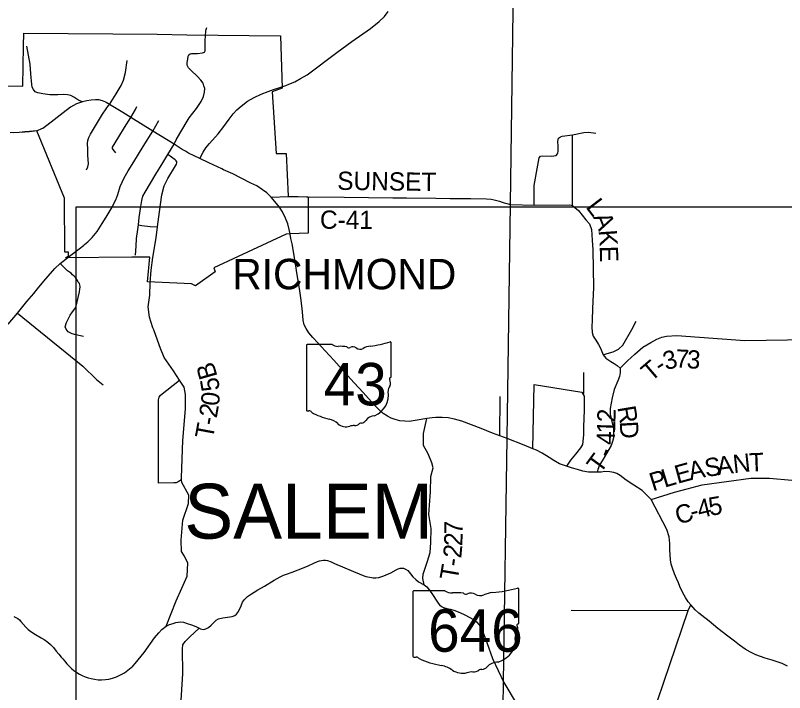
# Model space of a CAD drawing. Extents: x 2402298 to 2498138, y 789485 to 950881.
# Drawn here: x 2447192 to 2459820, y 881754 to 892870 of the extents above; entities that cross this region are included whole.
import ezdxf

# ---------------------------------------------------------------- set-up
doc = ezdxf.new("R2010")
doc.units = 0
for name, color, linetype in [('GM_X_City_Street', 7, 'Continuous'), ('GM_X_Corporation', 7, 'Continuous'), ('GM_X_Corporation_Text', 7, 'Continuous'), ('GM_X_County_Road', 7, 'Continuous'), ('GM_X_County_Road_Text', 7, 'Continuous'), ('GM_X_State_Route', 7, 'Continuous'), ('GM_X_State_Shield', 7, 'Continuous'), ('GM_X_Township', 7, 'Continuous'), ('GM_X_Township_Road', 7, 'Continuous'), ('GM_X_Township_Road_Text', 7, 'Continuous'), ('GM_X_Township_Text', 7, 'Continuous'), ('SH_Text', 7, 'Continuous')]:
    doc.layers.add(name, color=color, linetype=linetype)

msp = doc.modelspace()

# ---------------------------------------------------------------- linework, layer by layer
at = {"layer": 'GM_X_City_Street'}
msp.add_line((2449446, 890972), (2449548, 891146), dxfattribs=at)
for points in [[(2449164, 888933), (2449172, 889080), (2449179, 889207), (2449202, 889358), (2449215, 889434), (2449225, 889554), (2449249, 889734), (2449266, 889832), (2449286, 889901), (2449322, 889971), (2449499, 890265), (2449615, 890451), (2449697, 890586), (2449798, 890754), (2449834, 890825), (2449894, 890932), (2450047, 891186), (2450164, 891344), (2450240, 891455), (2450281, 891536), (2450299, 891607), (2450301, 891670), (2450287, 891712), (2450273, 891759), (2450235, 891808), (2450183, 891869), (2450073, 891972), (2450032, 892011), (2450014, 892053), (2450014, 892099), (2450022, 892151), (2450028, 892200), (2450040, 892225), (2450061, 892240), (2450082, 892247), (2450184, 892246), (2450263, 892253), (2450295, 892265), (2450309, 892290), (2450310, 892319), (2450310, 892434), (2450314, 892557), (2450317, 892591), (2450320, 892613), (2450326, 892637), (2450336, 892670)], [(2448292, 891452), (2448248, 891470), (2448200, 891497), (2448150, 891529), (2448101, 891553), (2448046, 891565), (2447987, 891569), (2447891, 891565), (2447760, 891564), (2447645, 891582), (2447561, 891598), (2447515, 891615), (2447487, 891652), (2447467, 891692), (2447462, 891737), (2447444, 891908), (2447436, 892069), (2447381, 892365)], [(2448357, 890333), (2448382, 890382), (2448391, 890434), (2448382, 890573), (2448380, 890674), (2448375, 890765), (2448381, 890815), (2448396, 890867), (2448423, 890919), (2448624, 891247), (2448681, 891338), (2448722, 891391), (2448738, 891407), (2448848, 891580), (2448927, 891718), (2448964, 891807), (2448998, 891931), (2449025, 892129)], [(2448841, 890613), (2448799, 890666), (2448786, 890687), (2448784, 890707), (2448889, 890876), (2448985, 891028), (2449088, 891192), (2449165, 891323), (2449186, 891375)], [(2449447, 888897), (2449504, 889218), (2449524, 889402), (2449560, 889643), (2449598, 889922), (2449637, 890072), (2449693, 890195), (2449820, 890398), (2449835, 890428), (2449842, 890448), (2449844, 890468), (2449834, 890485), (2449815, 890501), (2449697, 890586)], [(2449215, 889434), (2449268, 889419), (2449402, 889405), (2449524, 889402)]]:
    msp.add_lwpolyline(points, dxfattribs=at)
at = {"layer": 'GM_X_Corporation'}
msp.add_lwpolyline([(2446670, 891711), (2447313, 891708), (2447327, 892367), (2447333, 892576), (2449518, 892560), (2450009, 892551), (2451543, 892537), (2451569, 891675), (2451408, 891616), (2451471, 890604), (2451637, 890603), (2451669, 889901), (2451998, 889892), (2451998, 889298), (2451701, 889283), (2451638, 889279), (2450447, 888724), (2450472, 888663), (2450148, 888432), (2450083, 888465), (2449361, 888496), (2449397, 888901), (2449106, 888904), (2448017, 888889), (2448066, 888926), (2448066, 888981), (2448002, 888981), (2447996, 889869), (2447546, 890977), (2447425, 890963), (2447347, 890958), (2447252, 890950), (2447105, 890942)], dxfattribs=at)
at = {"layer": 'GM_X_County_Road'}
msp.add_line((2451708, 889897), (2451973, 889889), dxfattribs=at)
for points in [[(2451393, 889888), (2451670, 889898), (2451708, 889897)], [(2451973, 889889), (2451999, 889889), (2452588, 889887), (2453386, 889876), (2453612, 889875), (2454094, 889868), (2454332, 889862), (2454669, 889863), (2454928, 889860), (2455003, 889855), (2455051, 889845), (2455138, 889818), (2455181, 889805), (2455218, 889793), (2455237, 889788)], [(2455237, 889788), (2455262, 889781), (2455319, 889767), (2455709, 889755), (2456296, 889758), (2456337, 889748), (2456378, 889719), (2456434, 889669), (2456559, 889515), (2456614, 889446), (2456648, 889354), (2456658, 889178), (2456670, 889024), (2456680, 888403), (2456668, 888061), (2456659, 887869), (2456655, 887760), (2456659, 887665), (2456676, 887606), (2456718, 887538), (2456764, 887469), (2456800, 887407), (2456820, 887355), (2456841, 887297), (2456884, 887242), (2456966, 887188), (2457019, 887157), (2457069, 887125), (2457120, 887078), (2457120, 887006), (2457107, 886940), (2457080, 886873), (2457024, 886729), (2456989, 886594), (2456957, 886416), (2456955, 886323), (2456986, 886203), (2457013, 886082), (2457008, 885938), (2456996, 885876), (2456972, 885809), (2456855, 885615), (2456781, 885485), (2456752, 885415), (2456741, 885370)], [(2457627, 884923), (2458014, 885046), (2458222, 885097), (2458464, 885167), (2459267, 885275), (2459570, 885275), (2459938, 885242), (2460250, 885215), (2460668, 885203), (2461287, 885172), (2462299, 885114), (2462503, 885097), (2462703, 885107), (2463453, 885436), (2463907, 885464)]]:
    msp.add_lwpolyline(points, dxfattribs=at)
at = {"layer": 'GM_X_State_Route'}
for points in [[(2451680, 891739), (2451781, 891778), (2451873, 891836), (2451981, 891896), (2452470, 892261), (2452717, 892444), (2453024, 892656), (2453165, 892770), (2453250, 892849), (2453313, 892935)], [(2451430, 891651), (2451514, 891680), (2451634, 891721), (2451680, 891739)], [(2450221, 890521), (2450273, 890627), (2450317, 890696), (2450379, 890768), (2450521, 890927), (2450612, 891044), (2450700, 891167), (2450766, 891253), (2450827, 891319), (2450897, 891381), (2451005, 891460), (2451114, 891523), (2451224, 891577), (2451341, 891619), (2451430, 891651)], [(2448683, 891441), (2448678, 891444), (2448621, 891470), (2448561, 891484), (2448509, 891484), (2448438, 891476), (2448367, 891466), (2448292, 891452), (2448197, 891420), (2448098, 891364), (2447975, 891270), (2447830, 891154), (2447710, 891065), (2447641, 891016), (2447622, 891008)], [(2448953, 891275), (2448738, 891407), (2448683, 891441)], [(2449446, 890972), (2449088, 891192), (2448953, 891275)], [(2447622, 891008), (2447547, 890974), (2447426, 890960), (2447348, 890955), (2447253, 890947), (2447158, 890942)], [(2448329, 889107), (2448383, 889154), (2448455, 889224), (2448533, 889324), (2448615, 889455), (2448680, 889556), (2448766, 889696), (2448840, 889841), (2448871, 889932), (2448913, 890059), (2448976, 890205), (2449044, 890320), (2449137, 890467), (2449288, 890718), (2449446, 890972)], [(2449983, 890639), (2449929, 890670), (2449798, 890754), (2449446, 890972)], [(2450221, 890521), (2450033, 890611), (2449983, 890639)], [(2450609, 890336), (2450580, 890349), (2450367, 890449), (2450221, 890521)], [(2451701, 889285), (2451689, 889354), (2451664, 889449), (2451625, 889543), (2451575, 889646), (2451527, 889724), (2451451, 889816), (2451393, 889888), (2451318, 889958), (2451248, 890009), (2451154, 890073), (2451057, 890117), (2450900, 890200), (2450763, 890268), (2450609, 890336)], [(2457624, 884927), (2457544, 885014), (2457479, 885071), (2457344, 885158), (2457221, 885241), (2457122, 885315), (2457063, 885349), (2457017, 885368), (2456953, 885379), (2456866, 885381), (2456810, 885375), (2456741, 885370), (2456602, 885371), (2456505, 885390), (2456419, 885416), (2456338, 885439), (2456239, 885469), (2456126, 885510), (2456029, 885566), (2455953, 885615), (2455841, 885683), (2455748, 885735), (2455684, 885756), (2455546, 885813), (2455265, 885927), (2455143, 885969), (2455025, 886012), (2454840, 886087), (2454680, 886148), (2454523, 886210), (2454400, 886244), (2454295, 886263), (2454200, 886269), (2454096, 886270), (2454034, 886265), (2453948, 886255), (2453790, 886228), (2453656, 886206), (2453586, 886207), (2453503, 886217), (2453428, 886237), (2453360, 886260), (2453299, 886290), (2453230, 886336), (2453173, 886386), (2453101, 886458), (2452988, 886581), (2452899, 886681), (2452755, 886841), (2452588, 887022), (2452421, 887209), (2452279, 887362), (2452157, 887497), (2452077, 887582), (2452008, 887661), (2451963, 887732), (2451935, 887789), (2451915, 887866), (2451903, 888002), (2451885, 888195), (2451857, 888389), (2451818, 888612), (2451788, 888790), (2451755, 888992), (2451737, 889118), (2451715, 889208), (2451702, 889280), (2451701, 889285)], [(2448167, 888984), (2448309, 889091), (2448329, 889107)], [(2447074, 887802), (2447225, 887981), (2447382, 888172), (2447494, 888306), (2447557, 888380), (2447660, 888510), (2447729, 888592), (2447841, 888713), (2447927, 888796), (2448102, 888936), (2448167, 888984)], [(2459867, 882190), (2459777, 882234), (2459618, 882286), (2459503, 882319), (2459345, 882375), (2459258, 882418), (2459173, 882469), (2459080, 882534), (2458996, 882598), (2458890, 882680), (2458725, 882808), (2458583, 882925), (2458460, 883021), (2458411, 883058), (2458354, 883111), (2458282, 883194), (2458239, 883243), (2458194, 883314), (2458147, 883392), (2458099, 883498), (2458076, 883555), (2458046, 883627), (2458014, 883703), (2457979, 883797), (2457960, 883863), (2457944, 883932), (2457936, 884099), (2457933, 884204), (2457922, 884313), (2457888, 884433), (2457627, 884923), (2457624, 884927)], [(2449157, 882234), (2449308, 882411), (2449477, 882653), (2449546, 882733), (2449598, 882790), (2449666, 882844), (2449724, 882870), (2449780, 882889), (2449826, 882903), (2449864, 882912), (2449909, 882916), (2449952, 882912), (2450011, 882891), (2450084, 882865), (2450155, 882840), (2450207, 882812), (2450230, 882801), (2450253, 882795), (2450283, 882792), (2450319, 882801), (2450361, 882821), (2450404, 882862), (2450448, 882906), (2450488, 882942), (2450528, 882963), (2450599, 882982), (2450753, 883004), (2450796, 883020), (2450824, 883043), (2450854, 883085), (2450896, 883180), (2450922, 883236), (2450952, 883282), (2451001, 883330), (2451068, 883378), (2451114, 883405), (2451172, 883439), (2451280, 883501), (2451440, 883597), (2451539, 883654), (2451596, 883681), (2451644, 883700), (2451733, 883732), (2451907, 883795), (2452000, 883834), (2452093, 883879), (2452149, 883904), (2452185, 883916), (2452216, 883924), (2452251, 883929), (2452284, 883926), (2452318, 883920), (2452374, 883900), (2452432, 883875), (2452471, 883858), (2452564, 883818), (2452740, 883741), (2452835, 883702), (2452902, 883677), (2452945, 883662), (2453009, 883647), (2453063, 883638), (2453108, 883637), (2453157, 883646), (2453238, 883673), (2453357, 883721), (2453445, 883770), (2453476, 883787), (2453510, 883795), (2453538, 883798), (2453562, 883794), (2453597, 883782), (2453635, 883759), (2453678, 883701), (2453717, 883657), (2453764, 883611), (2453811, 883570), (2453902, 883522)], [(2453902, 883522), (2453948, 883489), (2454015, 883396), (2454061, 883329), (2454102, 883270), (2454133, 883222), (2454155, 883197), (2454188, 883169), (2454222, 883150), (2454273, 883136), (2454330, 883125), (2454391, 883108), (2454488, 883071), (2454569, 883032), (2454643, 882995), (2454711, 882955), (2454759, 882914), (2454802, 882872), (2454833, 882826), (2454849, 882789), (2454870, 882735), (2454932, 882575), (2455027, 882314), (2455208, 881922), (2455429, 881553)], [(2447164, 883002), (2447200, 882989), (2447233, 882971), (2447259, 882948), (2447283, 882921), (2447365, 882827), (2447403, 882790), (2447447, 882756), (2447523, 882709), (2447614, 882655), (2447665, 882625), (2447724, 882584), (2447770, 882542), (2447817, 882496), (2447862, 882436), (2447905, 882384), (2447945, 882337), (2447970, 882309)], [(2447970, 882309), (2447997, 882278), (2448037, 882227), (2448071, 882191), (2448112, 882152), (2448152, 882119), (2448203, 882082), (2448246, 882055), (2448287, 882035), (2448335, 882014), (2448384, 881997), (2448435, 881983), (2448492, 881973), (2448552, 881965), (2448607, 881964), (2448672, 881968), (2448728, 881976), (2448786, 881990), (2448850, 882013), (2448907, 882040), (2448982, 882079), (2449119, 882189), (2449157, 882234)]]:
    msp.add_lwpolyline(points, dxfattribs=at)
at = {"layer": 'GM_X_State_Shield'}
for p, q in [((2451970, 887451), (2451970, 886395)), ((2452391, 887470), (2451984, 887470)), ((2453362, 886943), (2453362, 887496)), ((2453362, 886943), (2453362, 886943)), ((2453718, 883408), (2453718, 882351)), ((2454244, 883426), (2453735, 883426)), ((2455458, 882899), (2455458, 883452)), ((2455458, 882899), (2455458, 882899))]:
    msp.add_line(p, q, dxfattribs=at)
for centre, radius, start, end in [((2452866, 888910), 1476, 275.8445, 288.9065), ((2453347, 887498), 15.5, 351.8621, 97.738), ((2451986, 887454), 16.1, 98.1301, 188.1301), ((2452488, 887592), 156, 231.6195, 271.1119), ((2452540, 886876), 562, 80.4867, 94.9883), ((2452668, 887459), 45.1, 219.7921, 297.1024), ((2452734, 887337), 93.8, 54.4667, 119.1411), ((2452855, 887505), 113, 233.8562, 294.8282), ((2453054, 887147), 297, 97.3462, 120.7689), ((2453358, 886902), 24, 107.944, 210.337), ((2453206, 886833), 144, 340.033, 23.6496), ((2453345, 886941), 16.6, 289.6038, 7.7341), ((2453417, 886712), 105, 136.8065, 186.9296), ((2452949, 886641), 369, 292.3089, 8.9858), ((2451986, 886392), 16.3, 171.9584, 258.3066), ((2451988, 886501), 124, 267.339, 280.6039), ((2452014, 886334), 44.8, 29.7484, 93.2717), ((2452579, 887283), 1066, 240.4129, 257.1985), ((2452261, 885920), 334, 47.1842, 75.836), ((2453104, 886098), 202, 94.4031, 142.5768), ((2452622, 886329), 212, 230.7004, 286.2918), ((2452744, 885963), 174, 85.6951, 111.2099), ((2452760, 886249), 113, 268.777, 315.5493), ((2452862, 886147), 31.8, 65.7517, 132.6484), ((2452848, 886292), 119, 282.8732, 323.2771)]:
    msp.add_arc(centre, radius, start, end, dxfattribs=at)
for centre, major_axis, start_param, end_param in [((2454838, 884866), (1845, 0), 4.814394, 5.042369), ((2455438, 883454), (19.4, 0), 6.141152, 7.989035), ((2453737, 883410), (20.2, 0), 1.712693, 3.28349), ((2454366, 883548), (196, 0), 4.042523, 4.731795), ((2454431, 882833), (702, 0), 1.404758, 1.657858), ((2454590, 883415), (56.4, 0), 3.836095, 5.185415), ((2454673, 883293), (117, 0), 0.950623, 2.079405), ((2454824, 883461), (141, 0), 4.081561, 5.145723), ((2455073, 883103), (371, 0), 1.699011, 2.107814), ((2455453, 882859), (30, 0), 1.883978, 3.671073), ((2455263, 882789), (180, 0), 5.934695, 6.695948), ((2455437, 882897), (20.7, 0), 5.05454, 6.418171), ((2455527, 882668), (131, 0), 2.387724, 3.262537), ((2454941, 882598), (462, 0), 5.101752, 6.440018), ((2453738, 882349), (20.3, 0), 3.00124, 4.508301), ((2453741, 882457), (155, 0), 4.665946, 4.897461), ((2453773, 882290), (56, 0), 0.519207, 1.627899), ((2454479, 883239), (1333, 0), 4.195997, 4.488961), ((2454082, 881876), (417, 0), 0.823519, 1.323587), ((2455136, 882054), (253, 0), 1.647645, 2.488434), ((2454533, 882285), (265, 0), 4.026481, 4.996735), ((2454686, 881919), (217, 0), 1.495662, 1.94098), ((2454705, 882206), (141, 0), 4.691044, 5.507374), ((2454833, 882103), (39.7, 0), 1.147584, 2.315152), ((2454816, 882249), (149, 0), 4.937069, 5.64225)]:
    msp.add_ellipse(centre, major_axis=major_axis, ratio=0.8, start_param=start_param, end_param=end_param, dxfattribs=at)
at = {"layer": 'GM_X_Township'}
msp.add_lwpolyline([(2460401, 871709), (2459688, 871718), (2455055, 871774), (2455087, 873978), (2455132, 876575), (2455173, 879496), (2455207, 881924), (2455264, 885930), (2455318, 889770), (2455396, 895324), (2455493, 902184), (2455511, 903524), (2455798, 903521), (2455910, 903520), (2460796, 903505)], dxfattribs=at)
at = {"layer": 'GM_X_Township_Road'}
for p, q in [((2455143, 885969), (2455148, 886612)), ((2456318, 883108), (2458235, 883104))]:
    msp.add_line(p, q, dxfattribs=at)
for points in [[(2455709, 889755), (2455708, 890080), (2455756, 890350), (2455790, 890533), (2455813, 890558), (2455845, 890566), (2455995, 890561), (2456070, 890568), (2456089, 890597), (2456099, 890616), (2456103, 890637), (2456104, 890721), (2456099, 890801), (2456100, 890828), (2456108, 890853), (2456138, 890878), (2456167, 890890), (2456335, 890911)], [(2456337, 889748), (2456335, 890911), (2456525, 890949), (2456599, 890953), (2456722, 890936)], [(2449463, 887706), (2449450, 887742), (2449394, 887915), (2449373, 888085), (2449397, 888275), (2449404, 888478), (2449422, 888689), (2449447, 888897)], [(2448312, 887599), (2448184, 887625), (2448125, 887642), (2448058, 887674), (2448024, 887717), (2448009, 887758), (2448033, 887831), (2448093, 887947), (2448132, 888003), (2448182, 888075), (2448244, 888333), (2448252, 888377), (2448253, 888417), (2448249, 888449), (2448242, 888471), (2448224, 888491), (2448210, 888516), (2448198, 888537), (2448180, 888567), (2448155, 888588), (2448132, 888613), (2448110, 888638), (2448079, 888654), (2448047, 888676), (2447927, 888796)], [(2447225, 887981), (2448300, 887112), (2448521, 886891), (2448631, 886805)], [(2456841, 887297), (2456905, 887320), (2457005, 887346), (2457094, 887392), (2457163, 887455), (2457310, 887715), (2457385, 887852)], [(2449576, 887404), (2449553, 887461), (2449463, 887706)], [(2457120, 887078), (2457241, 887199), (2457360, 887308), (2457492, 887422), (2457625, 887500), (2457720, 887554), (2457802, 887590), (2457881, 887603), (2458049, 887614), (2459168, 887531), (2460220, 887549)], [(2449666, 882844), (2449832, 883262), (2449923, 883466), (2450011, 883664), (2450023, 883881), (2449966, 883994), (2449917, 884071), (2449915, 884255), (2449938, 884584), (2450032, 884859), (2450037, 884993), (2449926, 885205), (2449920, 885244), (2449921, 885283), (2449938, 885893), (2449987, 886410), (2449982, 886648), (2449962, 886769), (2449888, 886882), (2449786, 887037), (2449636, 887256), (2449576, 887404)], [(2456512, 886646), (2456521, 886672), (2456523, 886723), (2456524, 887008)], [(2449920, 885244), (2449866, 885212), (2449833, 885199), (2449793, 885195), (2449540, 885190), (2449542, 886561), (2449552, 886606), (2449573, 886634), (2449888, 886882)], [(2455684, 885756), (2455709, 886809), (2456490, 886683), (2456528, 886619), (2456528, 886389), (2456518, 886114), (2456518, 885984), (2456504, 885826), (2456471, 885772), (2456389, 885667), (2456306, 885569), (2456239, 885469)], [(2453902, 883522), (2453878, 883627), (2453886, 883698), (2453959, 883909), (2454002, 884054), (2454011, 884220), (2454016, 884447), (2453981, 884680), (2453992, 884831), (2454005, 885050), (2454014, 885304), (2454049, 885443), (2454031, 885525), (2453966, 885672), (2453893, 885811), (2453889, 886009), (2453948, 886255)], [(2456969, 879683), (2457147, 880350), (2457633, 881329), (2458235, 883104), (2458282, 883194)], [(2450274, 879851), (2450275, 879857), (2450297, 879973), (2450320, 880088), (2450317, 880236), (2450375, 880333), (2450381, 880425), (2450369, 880489), (2450326, 880544), (2450278, 880469), (2450227, 880408), (2450186, 880371), (2450100, 880341), (2450010, 880331), (2449930, 880359), (2449864, 880434), (2449849, 880564), (2449938, 882067), (2449934, 882475), (2449941, 882537), (2449977, 882593), (2450053, 882672), (2450207, 882812)]]:
    msp.add_lwpolyline(points, dxfattribs=at)
at = {"layer": 'SH_Text'}
msp.add_lwpolyline([(2448187, 889729), (2496836, 889729), (2496836, 859271), (2448187, 859271)], close=True, dxfattribs=at)

# ---------------------------------------------------------------- texts
at = {"layer": 'GM_X_Corporation_Text'}
msp.add_text('RICHMOND', height=500, rotation=0, dxfattribs=at).set_placement((2450753, 888374))
at = {"layer": 'GM_X_County_Road_Text'}
for s, rotation, p in [('SUNSET', 359.2744, (2452474, 890007)), ('L', 307.3773, (2456546, 889722)), ('C-41', 359.6619, (2452191, 889368)), ('A', 292.2195, (2456672, 889562)), ('K', 274.0067, (2456766, 889342)), ('E', 271.7188, (2456784, 889082)), ('R', 279.4963, (2457073, 886438)), ('D', 273.2073, (2457112, 886203)), ('S', 8.2148, (2458526, 885292)), ('A', 7.5036, (2458725, 885321)), ('N', 6.0948, (2458985, 885355)), ('T', 2.1519, (2459242, 885383)), ('E', 15.3014, (2458061, 885180)), ('A', 12.1108, (2458273, 885238)), ('P', 17.4101, (2457656, 885056)), ('L', 16.5712, (2457848, 885116)), ('5', 9.4409, (2458596, 884654)), ('C', 16.2462, (2458071, 884509)), ('4', 13.852, (2458423, 884611)), ('-', 15.6248, (2458306, 884578))]:
    msp.add_text(s, height=300, rotation=rotation, dxfattribs=at).set_placement(p)
at = {"layer": 'GM_X_State_Shield'}
for s, p in [('43', (2452253, 886469)), ('646', (2453968, 882425))]:
    msp.add_text(s, height=696.1, dxfattribs=at).set_placement(p)
at = {"layer": 'GM_X_Township_Road_Text'}
for s, rotation, p in [('3', 15.6709, (2457870, 887043)), ('7', 357.1418, (2458023, 887090)), ('3', 355.9845, (2458206, 887081)), ('B', 106.0988, (2450512, 886945)), ('T', 40.6473, (2457627, 886846)), ('-', 32.7807, (2457788, 886986)), ('5', 99.5339, (2450551, 886726)), ('0', 83.0426, (2450530, 886449)), ('2', 80.2499, (2450497, 886251)), ('2', 88.5622, (2457042, 886187)), ('-', 79.6094, (2450474, 886126)), ('T', 79.4491, (2450433, 885904)), ('1', 88.194, (2457036, 886000)), ('4', 88.6761, (2457032, 885816)), ('-', 68.8952, (2456965, 885590)), ('T', 53.9213, (2456792, 885334)), ('7', 90.2412, (2454534, 884352)), ('2', 88.1426, (2454528, 884155)), ('2', 84.7276, (2454510, 883951)), ('T', 80.3594, (2454451, 883584)), ('-', 81.6487, (2454490, 883812))]:
    msp.add_text(s, height=300, rotation=rotation, dxfattribs=at).set_placement(p)
at = {"layer": 'GM_X_Township_Text'}
msp.add_text('SALEM', height=900, rotation=0, dxfattribs=at).set_placement((2449965, 884282))

doc.saveas('drawing.dxf')
